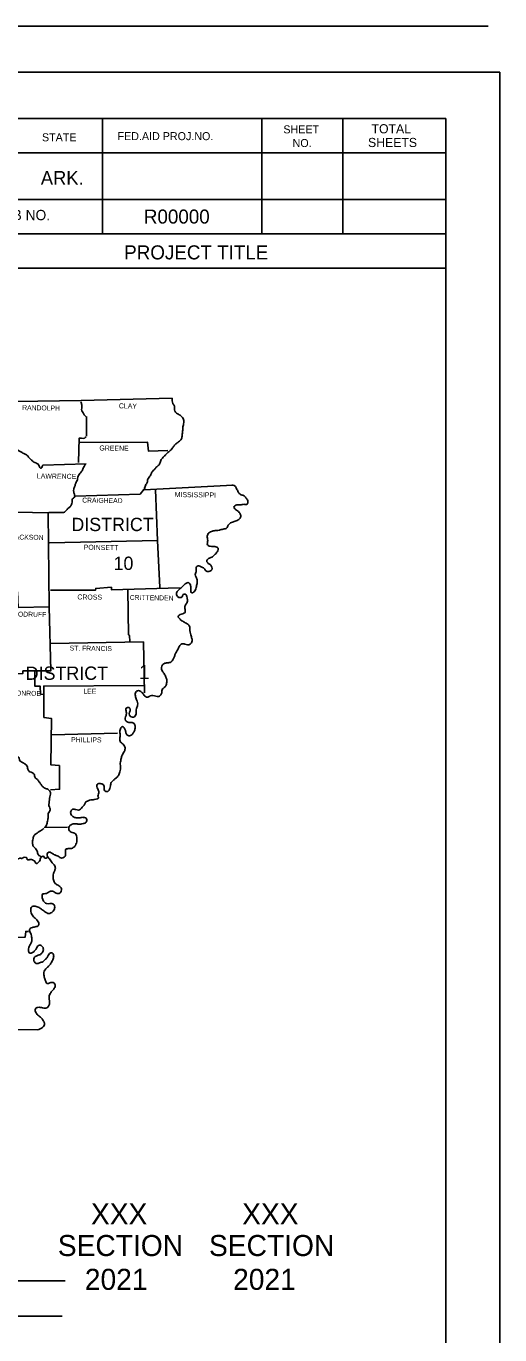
# Model space of a CAD drawing. Extents: x 76 to 6945, y -3933 to 2152.
# Drawn here: x 5436 to 5840, y -2489 to -1371 of the extents above; entities that cross this region are included whole.
import ezdxf

# ---------------------------------------------------------------- set-up
doc = ezdxf.new("R2010")
doc.units = 0
doc.layers.add('R_Draft', color=7, linetype='Continuous')
doc.layers.add('R_No Plot', color=7, linetype='Continuous')

msp = doc.modelspace()

# ---------------------------------------------------------------- linework, layer by layer
at = {"layer": 'R_Draft'}
for p, q in [((5830.6, -1370.7), (2320.8, -1370.7)), ((5830.6, -1410.1), (2557, -1410.1)), ((2632.6, -1449.6), (5794.4, -1449.6)), ((5501.3, -1449.6), (5501.3, -1548.2)), ((5637.1, -1449.6), (5637.1, -1548.2)), ((5706.4, -1449.6), (5706.4, -1548.2)), ((5794.4, -3504), (5794.4, -1449.6)), ((5794.4, -1478.9), (5363.5, -1478.9)), ((5794.4, -1478.6), (5794.4, -1478.6)), ((5794.4, -1518.9), (5363.5, -1518.9)), ((5794.4, -1548.2), (4971.7, -1548.2)), ((5363.5, -1577.5), (5794.4, -1577.5)), ((5536.7, -1766.8), (5537.9, -1763.1)), ((5537, -1765.6), (5538.2, -1762.7)), ((5451.3, -2055.6), (5471.3, -2055.3)), ((5151.3, -2443), (5469.4, -2443)), ((5101.3, -2473), (5466.6, -2473))]:
    msp.add_line(p, q, dxfattribs=at)
for points in [[(5012.1, -1693.3), (5173.8, -1693.4), (5315.7, -1693.1), (5483.1, -1690.5), (5560.7, -1688.7)], [(5407.6, -1692.3), (5407.3, -1694.7), (5409.3, -1695), (5409.2, -1696.2), (5411.5, -1696.7), (5411.7, -1698.3), (5412.8, -1699), (5413.1, -1703.8), (5418.8, -1704.4), (5418.8, -1708.7), (5420.9, -1709), (5420.9, -1710.7), (5422.7, -1711.2), (5422.6, -1717), (5424.2, -1717.3), (5424.6, -1730.4), (5416.1, -1731.2), (5416.2, -1734), (5413.6, -1734.1), (5414.5, -1785.7), (5454.8, -1786.6), (5455.5, -1866.8), (5429.2, -1867.5), (5428.7, -1854)], [(5487.5, -1704.3), (5487.5, -1721.2)], [(5480.7, -1743.7), (5481.2, -1722.8), (5481.2, -1726.5), (5539.7, -1726.2), (5540.5, -1734), (5557, -1733.4)], [(5450.1, -1745.9), (5487.2, -1744.6)], [(5477.7, -1772.3), (5533.2, -1770.5), (5536.5, -1766.7)], [(5536.7, -1766.8), (5612.6, -1762.9)], [(5546.3, -1766.9), (5548, -1810.2), (5550, -1850.5)], [(5467.9, -1786.4), (5455.7, -1786.4), (5454.8, -1786.6)], [(5548, -1810.2), (5455.9, -1812.3)], [(5456.7, -1852.8), (5495.3, -1852.6), (5495.4, -1851.2), (5508.8, -1850.2), (5508.8, -1852.3), (5567, -1850.7)], [(5522.8, -1852.3), (5523.3, -1890.8), (5524.2, -1891.4), (5524.5, -1896.6)], [(5522.8, -1852.3), (5523.3, -1890.8), (5524.2, -1891.4), (5524.5, -1896.6)], [(5522.8, -1852.3), (5523.3, -1890.8), (5524.2, -1891.4), (5524.5, -1896.6)], [(5522.8, -1852.3), (5523.3, -1890.8), (5524.2, -1891.4), (5524.5, -1896.6)], [(5522.8, -1852.3), (5523.3, -1890.8), (5524.2, -1891.4), (5524.5, -1896.6)], [(5455.5, -1866.8), (5457, -1921.6), (5433.2, -1921.7), (5433.1, -1923.9), (5426.2, -1924.3), (5425.6, -1935.7), (5417.2, -1935.7)], [(5456.7, -1898.3), (5536.1, -1896.7)], [(5536.1, -1896.7), (5536.9, -1940.5)], [(5536.1, -1896.7), (5536.9, -1940.5)], [(5536.1, -1896.7), (5536.9, -1940.5)], [(5536.1, -1896.7), (5536.9, -1940.5)], [(5536.1, -1896.7), (5536.9, -1940.5)], [(5536.1, -1896.7), (5536.9, -1940.5)], [(5536.1, -1896.7), (5536.9, -1940.5)], [(5536.1, -1896.7), (5536.9, -1940.5)], [(5443.4, -1922.2), (5443.3, -1934.6), (5447.9, -1934.6), (5448.1, -1941.5), (5451, -1941.8)], [(5456.7, -2023.3), (5464.5, -2022.8), (5464.4, -2002.5), (5457.1, -2002), (5457.5, -1962.3), (5451.2, -1961.4), (5451, -1934.7), (5536.3, -1934.1)], [(5457.7, -1976.4), (5514.1, -1975)], [(5448.9, -2080.5), (5449.8, -2080.4), (5450.5, -2080.1), (5451.2, -2080.4), (5451.4, -2081), (5452.2, -2081.7), (5453, -2081.8), (5453.6, -2081.3), (5454.2, -2080.5)], [(5079.1, -2146.9), (5079.3, -2227.8), (5445.8, -2228.4)], [(5409, -2143), (5422.4, -2143.8), (5423, -2149.6), (5435.1, -2149.2), (5435.6, -2144.3), (5437.9, -2144.3)]]:
    msp.add_lwpolyline(points, dxfattribs=at)
for points in [[(5482.6, -1691.8), (5483.5, -1694.3), (5483.4, -1697), (5483.4, -1699.5), (5484.7, -1701.2), (5486, -1703.3), (5487, -1704.2)], [(5560.7, -1688.7), (5561.2, -1693.1), (5562.6, -1695.4), (5562.8, -1699.6), (5564.5, -1701.4), (5567.4, -1703.2), (5570, -1706.1), (5570.6, -1709.5), (5569.8, -1713), (5569.6, -1716.9), (5569.2, -1720.3), (5568.6, -1723.4), (5566.2, -1725.9), (5563.9, -1727.7), (5561.8, -1729.8), (5560.3, -1732), (5557.7, -1734.4), (5555.1, -1736.9), (5553, -1739.1), (5550.9, -1741.9), (5549.9, -1745), (5547.6, -1747.2), (5545.8, -1749.2), (5543.4, -1751.9), (5542.2, -1754.6), (5539.9, -1757.7), (5539.4, -1760.7), (5537.9, -1763.1), (5537.8, -1763.5)], [(5487.1, -1721.5), (5485.8, -1722.8), (5483.3, -1722.8), (5481.2, -1722.8)], [(5425.7, -1729.5), (5427.9, -1731.8), (5429.8, -1733.7), (5432, -1734.8), (5434.6, -1736.3), (5436.9, -1737.5), (5438.4, -1739.4), (5440.5, -1741.5), (5442.6, -1743.2), (5445.9, -1744.8), (5447, -1746.5), (5448.5, -1748.6), (5450.1, -1745.9)], [(5486.9, -1744.7), (5485.4, -1747.1), (5484.2, -1749.9), (5481.8, -1753.1), (5480, -1756.2), (5479.7, -1758.3), (5478.3, -1761.1), (5477.5, -1763.9), (5476.6, -1766.3), (5476.6, -1768.8), (5477.3, -1771.3), (5477.1, -1773.6), (5475.6, -1774.7), (5475.2, -1777.6), (5474.6, -1779.6), (5473.3, -1781.6), (5471.4, -1783.1), (5469.4, -1785.4), (5467.9, -1786.4)], [(5611.5, -1763), (5612.6, -1762.9), (5616, -1766.5), (5617.5, -1769.5), (5619.7, -1771.2), (5622.2, -1772.1), (5624.1, -1774.4), (5625.4, -1776.9), (5624.7, -1779.1), (5621.9, -1779.3), (5618.8, -1779.8), (5615.8, -1779.7), (5613.4, -1781.7), (5615.6, -1784.4), (5618.5, -1786.9), (5619.3, -1789.6), (5617.7, -1792.2), (5614.5, -1793.6), (5611.4, -1794.8), (5608.6, -1797.2), (5607.3, -1799.5), (5604.2, -1800.5), (5601, -1801.4), (5598.2, -1801.7), (5595, -1802.3), (5591.9, -1803.8), (5590.6, -1806.4), (5591, -1810.1), (5590.9, -1814), (5594.2, -1815.3), (5597.1, -1815.4), (5599.9, -1816.9), (5599.6, -1819.1), (5597.5, -1821.9), (5595, -1824.1), (5592.5, -1825.2), (5590.2, -1827.3), (5591, -1829.4), (5593.1, -1830.8), (5594.6, -1833.1), (5594.4, -1835.2), (5592, -1836.7), (5589.4, -1836.1), (5587.5, -1833.6), (5585.3, -1832.8), (5583.4, -1831.9), (5581.2, -1833.2), (5581.2, -1836.1), (5580.4, -1839.2), (5581.1, -1841.5), (5582, -1844.7), (5581.9, -1847.1), (5581.1, -1850.5), (5579.4, -1854), (5577.4, -1855.1), (5576.6, -1851.3), (5576.2, -1848.2), (5575, -1846.4), (5573.4, -1846.3), (5571.3, -1847.8), (5569, -1850.1), (5566.1, -1852.6), (5564.4, -1855.1), (5565.3, -1858.2), (5567.5, -1859), (5569.2, -1858.4), (5570.1, -1856.4), (5571.8, -1856.1), (5573.4, -1859.2)], [(5573.4, -1859.2), (5573.8, -1862.1), (5572.1, -1865.2), (5571.5, -1868.3), (5571.8, -1871.4), (5568.6, -1873.1), (5565.8, -1875.1), (5567.4, -1877.5), (5570.4, -1879.7), (5573.4, -1881.4), (5575.3, -1883.1), (5575.8, -1887.2), (5576.3, -1889.8), (5577.3, -1893.4), (5577.7, -1895.9), (5575.9, -1898.9), (5573.8, -1899.5), (5571.6, -1898.8), (5569, -1898.6), (5566.9, -1900.6), (5565.4, -1903.4), (5563.9, -1906.2), (5562.8, -1908.6), (5561.7, -1911.2), (5559.5, -1914.2), (5556.8, -1914.7), (5553.6, -1915.5), (5551.7, -1917.7), (5552, -1921.4), (5553.8, -1923.9), (5555.2, -1927), (5556.2, -1929.7), (5555.7, -1933.1), (5554.3, -1935.6), (5552.5, -1937.1), (5551.7, -1940.3), (5550.4, -1942.7), (5549.2, -1943.5), (5546.8, -1943.3), (5544.2, -1942.8), (5542, -1943), (5539.9, -1944.1), (5537.8, -1943.4), (5535.6, -1941), (5533.8, -1939.2), (5531.8, -1938.5), (5529.7, -1939.6), (5529.3, -1942.9), (5530.3, -1946.3), (5531.2, -1950.9), (5530.3, -1953.7), (5530, -1958.3)], [(5530, -1958.3), (5527.7, -1961.2), (5524.3, -1959.4), (5524.3, -1957), (5524.8, -1954.5), (5523.6, -1952.9), (5521.5, -1953.6), (5521.5, -1956.7), (5521.3, -1959.7), (5520.7, -1964), (5522.1, -1965.3), (5525.3, -1965.7), (5527.6, -1966.3), (5529, -1968.6), (5528.9, -1971.4), (5527.8, -1974.1), (5526.2, -1976.3), (5523.7, -1977.1), (5521.7, -1975.8), (5520.9, -1973.2), (5520, -1970.9), (5518.3, -1969.2), (5516.5, -1971.1), (5516.1, -1974.6), (5516.2, -1977.6), (5516.2, -1981.7), (5518.8, -1984.4), (5520.4, -1987.5), (5519.9, -1990.3), (5518, -1993.6), (5517.2, -1996.5), (5516.4, -2000.4), (5516.5, -2004.7), (5515.8, -2008.9), (5514.4, -2011.7), (5511.8, -2014), (5510.1, -2015.5), (5508.7, -2017), (5508, -2020), (5507.5, -2022.1), (5505.6, -2024.6), (5504.1, -2024.8), (5502.9, -2023.8), (5502.5, -2022.1), (5502.5, -2020.4), (5501.7, -2018.7), (5499.2, -2018), (5497.2, -2018.1), (5496.3, -2019.5), (5497.6, -2023.4), (5498.1, -2025.9), (5497.4, -2029.3), (5497.8, -2029.7), (5494.2, -2031.6), (5491.3, -2031.9), (5488.9, -2032.6), (5486.6, -2034.1), (5485.5, -2036.3), (5483.9, -2038.1), (5482.5, -2039.8), (5480.6, -2040.6), (5478.5, -2040.2), (5475.7, -2039.9), (5474.1, -2041.9), (5474.6, -2044.8), (5476.5, -2046.5), (5479.3, -2047.3), (5482.2, -2047.1), (5485, -2046.8), (5487.6, -2048.2), (5487.1, -2050.9), (5484.6, -2052.2), (5480.9, -2052.6), (5477.9, -2052.3), (5474.3, -2053.1), (5472.5, -2055.4), (5473.5, -2058.9), (5477.4, -2060.3), (5479.2, -2063.6), (5479.3, -2066.7), (5478, -2070.8), (5476.2, -2072.7), (5472.7, -2073.5), (5470, -2074), (5469.6, -2078.6), (5468.4, -2080.9), (5466.3, -2081.6), (5463.3, -2080.1), (5461.5, -2079.4), (5459.3, -2078.4), (5456.5, -2076.7), (5454.4, -2077), (5455, -2081.4), (5455.2, -2081.6), (5457.6, -2084.9), (5460, -2087.5), (5461.1, -2090.6)], [(5426.4, -1990.5), (5426.7, -1994.6), (5429.1, -1995.2), (5430.1, -1996.3), (5430.6, -1998.6), (5432.3, -1999.6), (5434.6, -2001), (5436, -2002), (5437, -2003.6), (5437.6, -2006.2), (5439.2, -2007.9), (5441.4, -2008.7), (5443, -2010.6), (5444, -2013.3), (5445.6, -2014.5), (5447.2, -2016.6), (5448, -2017.5), (5449.4, -2019.9), (5450.8, -2021.1), (5451.8, -2021.8), (5453.4, -2022.3), (5455.4, -2023.6), (5456.7, -2025.6), (5456.7, -2027.1), (5456.2, -2029.4), (5455.8, -2031.8), (5455.6, -2034.5), (5455.4, -2036.9), (5456.3, -2038.9), (5455.8, -2041.9), (5454.8, -2043.5), (5454.7, -2045.7), (5454.4, -2049), (5454, -2050.9), (5453.1, -2054), (5451.8, -2055.6)], [(5388.4, -2042.2), (5389.9, -2043.2), (5392, -2043.1), (5393.4, -2042.5), (5394.5, -2042.6), (5396, -2043.5), (5397, -2044.7), (5397.7, -2045.6), (5398.2, -2047), (5398.2, -2048.3), (5398.7, -2050.1), (5399.3, -2050.8), (5400.1, -2052.1), (5400.6, -2053.3), (5400.9, -2054.1), (5402, -2055.4), (5403, -2055.3), (5403.9, -2055.4), (5405.1, -2056.1), (5406.9, -2057.5), (5407.2, -2057.9), (5408.4, -2060.5), (5408.6, -2062.1), (5408.8, -2064.2), (5409.2, -2066.2), (5410, -2068.4), (5410.4, -2069.9), (5411.3, -2072), (5411.9, -2073.4), (5412.7, -2075.2), (5413.9, -2077.2), (5414.4, -2078.4), (5416.1, -2078.3), (5417.3, -2077.8), (5418.2, -2077), (5419.3, -2077.1), (5420.5, -2077.5), (5422.1, -2077.8), (5423.1, -2077.2), (5423.6, -2076.8), (5423.7, -2075.9), (5424.6, -2075.4), (5425.6, -2076.1), (5426.7, -2077.7), (5426.7, -2078.7), (5426.3, -2079.3), (5425, -2080.1), (5423.2, -2080.7), (5422.7, -2081.4), (5424.4, -2082.2), (5427.1, -2082.4), (5427.8, -2081.8), (5429.6, -2082.3), (5430.3, -2081.8), (5432.7, -2081.9), (5433.8, -2081.1), (5436, -2081.2), (5436.7, -2081.7), (5436.7, -2082.6), (5438.5, -2083), (5439.8, -2082.7), (5441.5, -2083.2), (5443, -2084), (5443.8, -2085.1), (5444.8, -2086.3), (5445.7, -2086), (5446.4, -2085.1), (5447.9, -2083.5), (5447.9, -2082.5), (5448.3, -2081.8), (5448.8, -2080.8)], [(5451.1, -2056.2), (5449, -2057.9), (5447.2, -2058.9), (5445.3, -2060.3), (5443, -2062), (5441.9, -2064.9), (5441.3, -2068.9), (5442.1, -2071.3), (5443.9, -2073.4), (5445.1, -2075.1), (5446, -2078.1), (5448.2, -2080.2), (5448.9, -2080.5)], [(5461.1, -2090.6), (5460.1, -2092.9), (5459, -2096.9), (5459.3, -2100.3), (5460.8, -2103.2), (5463.2, -2104.8), (5465.8, -2107.1), (5465.6, -2110.6), (5464.1, -2111.9), (5460.6, -2111), (5457.9, -2109.8), (5455.6, -2110.5), (5452.5, -2112), (5450.2, -2112.3), (5450.3, -2117.1), (5453.4, -2120.5), (5456.1, -2120.5), (5459.2, -2120.9), (5460.3, -2124.5), (5458.5, -2127.5), (5455.5, -2129), (5451.7, -2127.2), (5449, -2125.3), (5446.3, -2123.5), (5442.9, -2122.6), (5441, -2123), (5440.1, -2127.2), (5441.7, -2131), (5444.3, -2133.6), (5446.7, -2137), (5446.3, -2139.5), (5444.5, -2140.2), (5441.3, -2140.9), (5439.4, -2141.9), (5438.9, -2142.7), (5439.9, -2146.1), (5440.8, -2149.8), (5440.8, -2152.6), (5439.7, -2155.2), (5438, -2159.2), (5438.2, -2161.8), (5439.4, -2163), (5440.9, -2162.6), (5442.9, -2161.2), (5444.2, -2159.6), (5445.3, -2157.6), (5447.4, -2155.9), (5450, -2157.4), (5450.6, -2160.5), (5449.1, -2163.2), (5447, -2164.4), (5444.4, -2165.4), (5442.5, -2167.6), (5443, -2170.2), (5444.5, -2171.6), (5448.2, -2170.9), (5450.7, -2169.8), (5452.1, -2168.4), (5453.8, -2166.7), (5454.7, -2165), (5456, -2163.2), (5458.3, -2162.7), (5459.4, -2164.2), (5459, -2167.6), (5457.6, -2170.8), (5455.7, -2173.5), (5453.6, -2175.4), (5451, -2179.5), (5451.5, -2183.3), (5452.5, -2186.4), (5453.9, -2188.8), (5456.3, -2188.3), (5459, -2188), (5460.6, -2189.3), (5460.4, -2192.1), (5458.4, -2194.8), (5456.5, -2197.4), (5455.5, -2201), (5455.9, -2203.5), (5455.9, -2205.8), (5455.1, -2208.3), (5453.7, -2209.7), (5450, -2209.6), (5446.1, -2209.2), (5444, -2210.4), (5444.4, -2213.8), (5446.7, -2216.3), (5448.3, -2217.6), (5450.6, -2220.4), (5451.6, -2222.7), (5451.3, -2224.7), (5449.9, -2226.4), (5445.8, -2228.4)]]:
    msp.add_spline(points, degree=3, dxfattribs=at)
at = {"layer": 'R_No Plot'}
msp.add_lwpolyline([(2557, -1410.1), (5840.4, -1410.1), (5840.4, -3543.4), (2557, -3543.4)], close=True, dxfattribs=at)

# ---------------------------------------------------------------- texts
at = {"layer": 'R_Draft'}
for s, height, p in [('STATE', 6.84, (5449.5, -1469.1)), ('FED.AID PROJ.NO.', 6.841, (5514, -1468.1)), ('SHEET', 6.84, (5655.6, -1462.3)), ('TOTAL', 7.82, (5730.9, -1462.3)), ('NO.', 6.84, (5663.5, -1474)), ('SHEETS', 7.82, (5727.9, -1474)), ('ARK.', 11.72, (5448.5, -1506.2)), ('JOB NO.', 8.79, (5409.4, -1536.5)), ('R00000', 12, (5536.5, -1539.4)), ('PROJECT TITLE', 12, (5519.7, -1570)), ('DISTRICT', 11.4, (5474.6, -1802.2)), ('10', 11.4, (5510.6, -1835.4)), ('DISTRICT', 11.4, (5435.6, -1929.3)), ('1', 12, (5532.4, -1928.6)), ('XXX', 18, (5491.3, -2394.7)), ('XXX', 18, (5620.4, -2394.7)), ('SECTION', 18, (5463, -2421.7)), ('SECTION', 18, (5592.1, -2421.7)), ('2021', 18, (5486.1, -2450.6)), ('2021', 18, (5612.7, -2450.6))]:
    msp.add_text(s, height=height, dxfattribs=at).set_placement(p)
for s, height, rotation, p in [('RANDOLPH', 4.2, 359.2583, (5432.6, -1698.8)), ('CLAY', 4.3, 359.2258, (5515.1, -1697.3)), ('GREENE', 4.3, 359.2361, (5498.5, -1733.3)), ('LAWRENCE', 4.3, 359.2678, (5445.1, -1757.2)), ('CRAIGHEAD', 4.2, 359.1159, (5483.8, -1777.8)), ('MISSISSIPPI', 4.299, 359.3097, (5562.8, -1773.1)), ('JACKSON', 4.2, 359.1352, (5423.4, -1809.3)), ('POINSETT', 4.3, 359.1987, (5485.1, -1818.1)), ('CROSS', 4.3, 359.3839, (5479.7, -1860.6)), ('CRITTENDEN', 4.2, 359.213, (5524.4, -1861)), ('WOODRUFF', 4.2, 359.2748, (5419, -1875.1)), ('ST. FRANCIS', 4.199, 359.2216, (5473.1, -1904.2)), ('MONROE', 4.2, 359.0331, (5422.5, -1942.6)), ('LEE', 4.3, 359.4327, (5484.8, -1941.1)), ('PHILLIPS', 4.3, 359.3179, (5474.3, -1982.5))]:
    msp.add_text(s, height=height, rotation=rotation, dxfattribs=at).set_placement(p)

doc.saveas('drawing.dxf')
